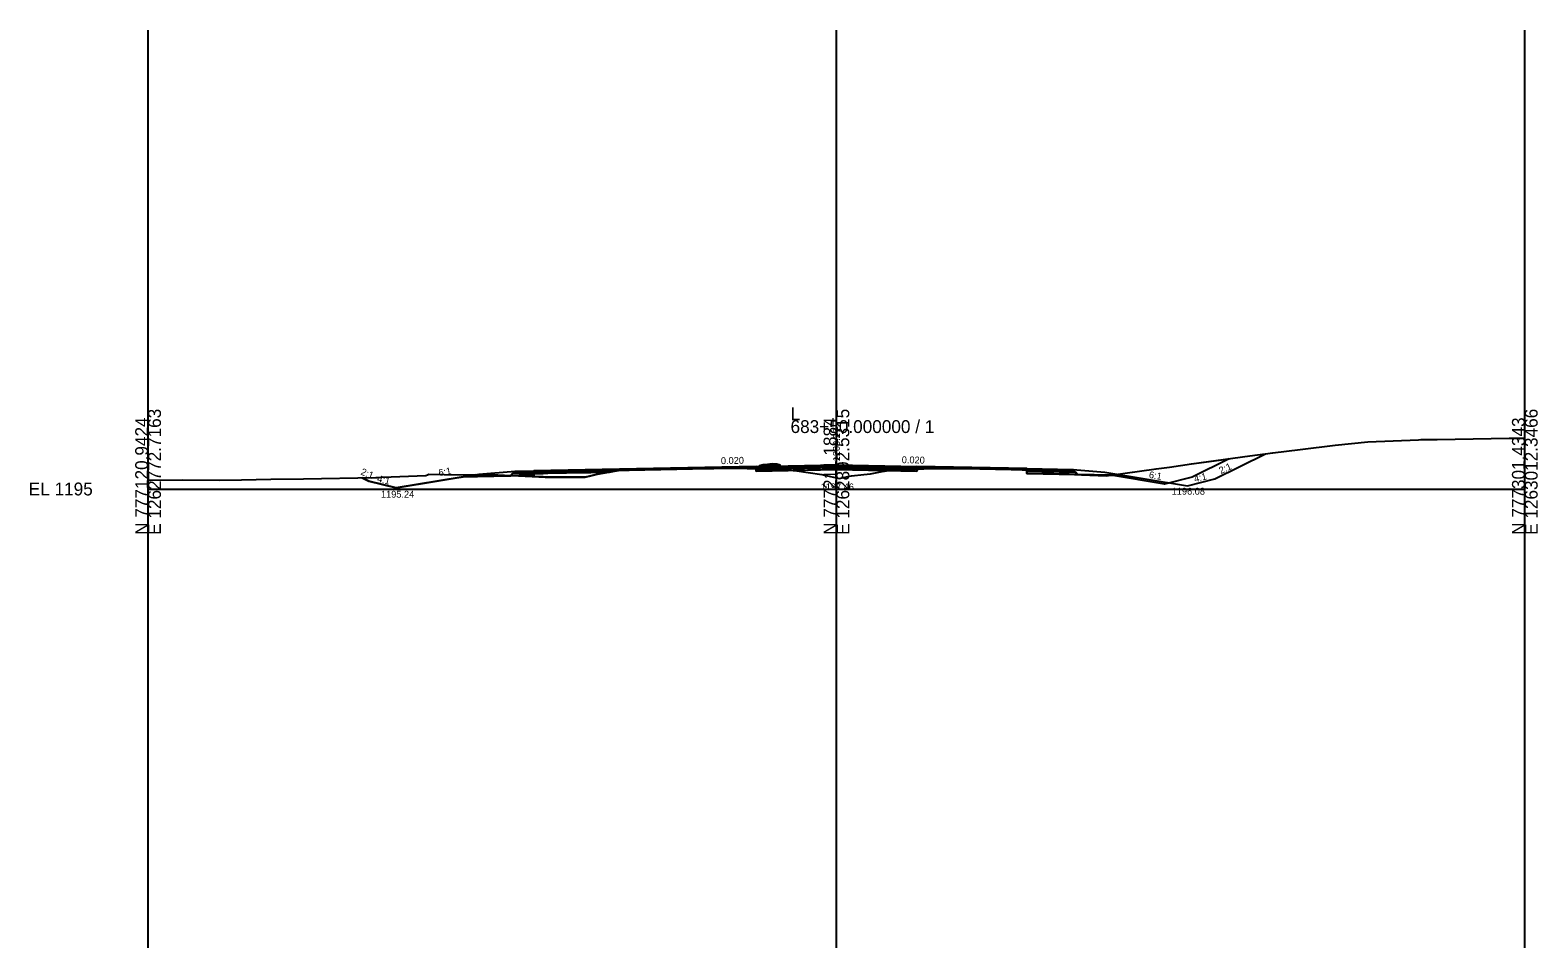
# Model space of a CAD drawing. Extents: x -41 to 1262860, y -100 to 777489.
# Drawn here: x 974.3 to 1302.8, y 330 to 530 of the extents above; entities that cross this region are included whole.
import ezdxf

# ---------------------------------------------------------------- set-up
doc = ezdxf.new("R2010")
doc.units = 0
for name, color, linetype in [('Exist Cross Section Cell', 7, 'Continuous'), ('Exist XS Center Line Elevation Label', 7, 'Continuous'), ('Exist XS Ground Line', 7, 'Continuous'), ('Prop CMT Pvmt Course 1', 7, 'Continuous'), ('Prop CMT Pvmt Surface', 7, 'Continuous'), ('Prop CMT Shld Paved Course 1', 7, 'Continuous'), ('Prop CMT Shld Paved Course 2', 7, 'Continuous'), ('Prop CMT Shld Paved Course 4', 7, 'Continuous'), ('Prop CMT Subgrade Earthwork', 7, 'Continuous'), ('Prop Conc Curb and Gutter', 7, 'Continuous'), ('Prop Conc Island Cover', 7, 'Continuous'), ('Prop XS Ditch Standard Text', 7, 'Continuous'), ('Prop XS Earthwork Shape', 7, 'Continuous'), ('Prop XS Exc Vertical Line 1', 7, 'Continuous'), ('Prop XS Exc Vertical Line 2', 7, 'Continuous'), ('Prop XS Exc Vertical Line 3', 7, 'Continuous'), ('Prop XS Finish Grade', 7, 'Continuous'), ('Prop XS Hydro Elevations', 7, 'Continuous'), ('Prop XS SE Text', 7, 'Continuous'), ('Prop XS Side Slope Text', 7, 'Continuous'), ('Scratch_Level_4', 7, 'Continuous'), ('Scratch_Level_6', 7, 'Continuous')]:
    doc.layers.add(name, color=color, linetype=linetype)

msp = doc.modelspace()

# ---------------------------------------------------------------- linework, layer by layer
at = {"layer": 'Exist Cross Section Cell'}
for p, q in [((1150, 430), (1150, 445)), ((1000, 430), (1150, 430)), ((1150, 430), (1300, 430))]:
    msp.add_line(p, q, dxfattribs=at)
at = {"layer": 'Exist XS Ground Line'}
msp.add_lwpolyline([(1000, 431.95), (1000.61, 431.96), (1007.45, 432), (1015.59, 431.96), (1020.38, 432.01), (1026.75, 432.13), (1033.88, 432.24), (1049.62, 432.51), (1050.17, 432.53), (1050.92, 432.55), (1052.97, 432.63), (1060.5, 432.91), (1060.92, 433.12), (1061.15, 433.23), (1064.52, 433.18), (1069.32, 433.12), (1072.47, 433.1), (1076.21, 433.08), (1085.13, 432.67), (1086.12, 432.63), (1086.5, 432.61), (1087.11, 432.59), (1095.24, 432.58), (1096.5, 432.88), (1097.97, 433.26), (1100.43, 433.68), (1102.95, 434.14), (1106.38, 434.2), (1107.34, 434.23), (1107.61, 434.25), (1110.51, 434.43), (1122.21, 434.57), (1123.26, 434.58), (1134.15, 434.42), (1135.14, 434.4), (1139.22, 434.2), (1139.55, 434.18), (1140.88, 434), (1146.81, 433.16), (1148.74, 432.75), (1150.67, 432.31), (1152.48, 432.7), (1153.28, 432.88), (1156, 433.16), (1157.43, 433.33), (1159.95, 433.8), (1161.39, 434.02), (1164.17, 434.19), (1165.36, 434.27), (1169.02, 434.36), (1177.5, 434.54), (1186.41, 434.33), (1189.64, 434.26), (1192.3, 434.1), (1193.19, 434.05), (1194.78, 433.81), (1197.3, 433.35), (1203.43, 433.11), (1203.46, 433.11), (1208.81, 432.9), (1219.67, 434.38), (1222.6, 434.76), (1227.34, 435.5), (1240.06, 437.22), (1245.06, 437.9), (1251.03, 438.62), (1258.65, 439.53), (1265.79, 440.28), (1276.86, 440.74), (1277.37, 440.76), (1277.76, 440.76), (1280.93, 440.82), (1296.61, 441.05), (1300, 441.1)], dxfattribs=at)
at = {"layer": 'Prop CMT Pvmt Course 1'}
for p, q in [((1132.5, 434.67), (1150, 435.02)), ((1150, 435.02), (1167.5, 434.67))]:
    msp.add_line(p, q, dxfattribs=at)
for points in [[(1084.08, 433.95), (1084.08, 433.7), (1084.08, 433.7), (1132.5, 434.67), (1132.5, 434.92), (1132.5, 434.92), (1084.08, 433.95), (1084.08, 433.95), (1084.08, 433.95)], [(1191.5, 434.44), (1191.5, 434.44), (1167.5, 434.92), (1167.5, 434.92), (1167.5, 434.92), (1167.5, 434.67), (1167.5, 434.67), (1191.5, 434.19), (1191.5, 434.44)]]:
    msp.add_lwpolyline(points, dxfattribs=at)
at = {"layer": 'Prop CMT Pvmt Surface'}
for p, q in [((1079.96, 433.87), (1084.08, 433.95)), ((1084.08, 433.95), (1132.5, 434.92)), ((1132.5, 434.92), (1150, 435.27)), ((1150, 435.27), (1167.5, 434.92)), ((1167.5, 434.92), (1191.5, 434.44)), ((1191.5, 434.44), (1201.5, 434.24))]:
    msp.add_line(p, q, dxfattribs=at)
at = {"layer": 'Prop CMT Shld Paved Course 1'}
for p, q in [((1191.5, 434.44), (1191.5, 434.44)), ((1191.5, 434.44), (1191.5, 434.44)), ((1191.5, 434.44), (1191.5, 434.19)), ((1191.5, 434.19), (1191.5, 434.19)), ((1191.5, 434.19), (1201.76, 433.99)), ((1195.5, 434.36), (1195.5, 434.36)), ((1201.76, 433.99), (1201.5, 434.24))]:
    msp.add_line(p, q, dxfattribs=at)
msp.add_lwpolyline([(1079.96, 433.87), (1084.08, 433.95), (1084.08, 433.95), (1084.08, 433.7), (1079.71, 433.62), (1079.71, 433.62), (1079.71, 433.62), (1079.96, 433.87), (1080.08, 433.87)], dxfattribs=at)
at = {"layer": 'Prop CMT Shld Paved Course 2'}
for p, q in [((1085.13, 433.72), (1084.08, 433.7)), ((1084.08, 433.7), (1084.08, 433.7)), ((1084.08, 433.7), (1084.08, 433.7)), ((1084.08, 433.7), (1084.08, 433.37)), ((1086.12, 433.74), (1085.13, 433.72)), ((1086.5, 433.75), (1086.12, 433.74)), ((1087.11, 433.76), (1086.5, 433.75)), ((1095.24, 433.93), (1087.11, 433.76)), ((1087.11, 433.76), (1087.11, 433.76)), ((1087.11, 433.76), (1087.11, 433.76)), ((1087.11, 433.76), (1087.11, 433.76)), ((1096.5, 433.95), (1095.24, 433.93)), ((1095.24, 433.93), (1095.24, 433.93)), ((1097.97, 433.98), (1096.5, 433.95)), ((1096.5, 433.95), (1096.5, 433.95)), ((1100.43, 434.03), (1097.97, 433.98)), ((1097.97, 433.98), (1097.97, 433.98)), ((1097.97, 433.98), (1097.97, 433.98)), ((1097.97, 433.65), (1100.43, 433.7)), ((1102.95, 434.08), (1100.43, 434.03)), ((1100.43, 434.03), (1100.43, 434.03)), ((1100.43, 433.7), (1100.43, 433.7)), ((1100.43, 433.7), (1100.56, 433.7)), ((1100.56, 433.7), (1102.6, 434.07)), ((1100.56, 433.7), (1100.56, 433.7)), ((1102.6, 434.07), (1102.95, 434.08)), ((1102.6, 434.07), (1102.6, 434.07)), ((1106.38, 434.15), (1102.95, 434.08)), ((1102.95, 434.08), (1106.38, 434.15)), ((1102.95, 434.08), (1102.95, 434.08)), ((1102.95, 434.08), (1102.95, 434.08)), ((1107.34, 434.17), (1106.38, 434.15)), ((1106.38, 434.15), (1107.34, 434.17)), ((1106.38, 434.15), (1106.38, 434.15)), ((1106.38, 434.15), (1106.38, 434.15)), ((1107.61, 434.17), (1107.34, 434.17)), ((1107.34, 434.17), (1107.61, 434.17)), ((1110.51, 434.23), (1107.61, 434.17)), ((1107.61, 434.17), (1110.51, 434.23)), ((1107.61, 434.17), (1107.61, 434.17)), ((1107.61, 434.17), (1107.61, 434.17)), ((1122.21, 434.47), (1110.51, 434.23)), ((1110.51, 434.23), (1122.21, 434.47)), ((1110.51, 434.23), (1110.51, 434.23)), ((1110.51, 434.23), (1110.51, 434.23)), ((1110.51, 434.23), (1110.51, 434.23)), ((1110.51, 434.23), (1110.51, 434.23)), ((1123.26, 434.49), (1122.21, 434.47)), ((1122.21, 434.47), (1123.26, 434.49)), ((1122.21, 434.47), (1122.21, 434.47)), ((1122.21, 434.47), (1122.21, 434.47)), ((1132.5, 434.67), (1123.26, 434.49)), ((1123.26, 434.49), (1125.9, 434.54)), ((1123.26, 434.49), (1123.26, 434.49)), ((1125.9, 434.54), (1125.9, 434.54)), ((1125.9, 434.54), (1125.9, 434.54)), ((1125.9, 434.54), (1132.5, 434.44)), ((1132.5, 434.34), (1150, 434.69)), ((1132.5, 434.44), (1132.5, 434.67)), ((1132.5, 434.67), (1132.5, 434.67)), ((1132.5, 434.67), (1132.5, 434.67)), ((1132.5, 434.44), (1132.5, 434.34)), ((1132.5, 434.44), (1132.5, 434.44)), ((1150, 434.69), (1167.5, 434.34)), ((1169.02, 434.64), (1167.5, 434.67)), ((1167.5, 434.67), (1167.5, 434.67)), ((1167.5, 434.67), (1167.5, 434.34)), ((1167.5, 434.34), (1167.9, 434.33)), ((1167.9, 434.33), (1169.02, 434.36)), ((1167.9, 434.33), (1167.9, 434.33)), ((1177.5, 434.47), (1169.02, 434.64)), ((1169.02, 434.64), (1169.02, 434.64)), ((1169.02, 434.36), (1175.93, 434.5)), ((1169.02, 434.36), (1169.02, 434.36)), ((1175.93, 434.5), (1175.93, 434.5)), ((1175.93, 434.5), (1177.5, 434.47)), ((1186.41, 434.29), (1177.5, 434.47)), ((1177.5, 434.47), (1177.5, 434.47)), ((1177.5, 434.47), (1177.5, 434.47)), ((1177.5, 434.47), (1177.5, 434.47)), ((1177.5, 434.47), (1177.5, 434.47)), ((1177.5, 434.47), (1186.41, 434.29)), ((1189.64, 434.23), (1186.41, 434.29)), ((1186.41, 434.29), (1186.41, 434.29)), ((1186.41, 434.29), (1186.41, 434.29)), ((1186.41, 434.29), (1189.64, 434.23)), ((1191.5, 434.19), (1189.64, 434.23)), ((1189.64, 434.23), (1189.64, 434.23)), ((1189.64, 434.23), (1189.64, 434.23)), ((1189.64, 434.23), (1190.44, 434.21)), ((1190.44, 434.21), (1190.44, 434.21)), ((1190.44, 434.21), (1191.5, 434.15)), ((1191.5, 434.19), (1191.5, 434.19)), ((1191.5, 434.19), (1191.5, 434.19)), ((1191.5, 434.19), (1191.5, 433.86)), ((1191.5, 434.15), (1191.5, 434.19)), ((1191.5, 434.19), (1191.5, 434.19)), ((1191.5, 434.19), (1191.5, 434.19)), ((1191.5, 434.15), (1191.5, 434.15)), ((1191.5, 433.86), (1191.5, 433.86)), ((1191.5, 433.86), (1202.1, 433.65)), ((1202.1, 433.65), (1201.76, 433.99)), ((1084.08, 433.37), (1085.13, 433.39)), ((1084.08, 433.37), (1084.08, 433.37)), ((1085.13, 433.39), (1086.12, 433.41)), ((1086.12, 433.41), (1086.5, 433.42)), ((1086.5, 433.42), (1087.11, 433.43)), ((1087.11, 433.43), (1095.24, 433.59)), ((1087.11, 433.43), (1087.11, 433.43)), ((1087.11, 433.43), (1087.11, 433.43)), ((1087.11, 433.43), (1087.11, 433.43)), ((1095.24, 433.59), (1096.5, 433.62)), ((1095.24, 433.59), (1095.24, 433.59)), ((1096.5, 433.62), (1097.97, 433.65)), ((1096.5, 433.62), (1096.5, 433.62)), ((1097.97, 433.65), (1097.97, 433.65)), ((1097.97, 433.65), (1097.97, 433.65))]:
    msp.add_line(p, q, dxfattribs=at)
msp.add_lwpolyline([(1079.71, 433.62), (1084.08, 433.7), (1084.08, 433.7), (1084.08, 433.37), (1079.37, 433.28), (1079.37, 433.28), (1079.37, 433.28), (1079.71, 433.62), (1079.83, 433.62)], dxfattribs=at)
at = {"layer": 'Prop CMT Shld Paved Course 4'}
for p, q in [((1100.43, 433.68), (1097.97, 433.26)), ((1100.56, 433.7), (1100.43, 433.68)), ((1132.5, 434.34), (1132.5, 433.88)), ((1132.5, 433.88), (1150, 434.23)), ((1150, 434.23), (1167.5, 433.88)), ((1167.5, 434.34), (1167.5, 433.88)), ((1167.9, 434.33), (1167.5, 434.32)), ((1191.5, 433.86), (1191.5, 433.86)), ((1191.5, 433.86), (1191.5, 433.86)), ((1191.5, 433.86), (1191.5, 433.4)), ((1085.13, 432.67), (1084.08, 432.72)), ((1086.12, 432.63), (1085.13, 432.67)), ((1086.5, 432.61), (1086.12, 432.63)), ((1087.11, 432.59), (1086.5, 432.61)), ((1095.24, 432.58), (1087.11, 432.59)), ((1096.5, 432.88), (1095.24, 432.58)), ((1097.97, 433.26), (1096.5, 432.88)), ((1191.5, 433.4), (1204.56, 433.14)), ((1202.56, 433.18), (1202.1, 433.65))]:
    msp.add_line(p, q, dxfattribs=at)
msp.add_lwpolyline([(1079.37, 433.28), (1084.08, 433.37), (1084.08, 433.37), (1084.08, 432.91), (1078.9, 432.81), (1078.9, 432.81), (1078.9, 432.81), (1079.37, 433.28), (1079.37, 433.28), (1079.37, 433.28), (1079.49, 433.28)], dxfattribs=at)
at = {"layer": 'Prop CMT Subgrade Earthwork'}
for p, q in [((1132.5, 434.44), (1132.5, 433.88)), ((1132.5, 433.88), (1150, 434.23)), ((1150, 434.23), (1167.5, 433.88)), ((1167.5, 433.88), (1167.5, 434.32)), ((1191.5, 434.15), (1191.5, 433.4)), ((1084.08, 432.91), (1068.2, 432.59)), ((1084.08, 432.91), (1084.08, 432.72)), ((1191.5, 433.4), (1212.73, 432.97))]:
    msp.add_line(p, q, dxfattribs=at)
at = {"layer": 'Prop Conc Curb and Gutter'}
for p, q in [((1133.25, 434.94), (1133.26, 435.1)), ((1133.25, 434.94), (1133.25, 434.94)), ((1133.25, 434.94), (1133.25, 434.81)), ((1135.01, 434.94), (1133.25, 434.94)), ((1133.25, 434.94), (1133.25, 434.94)), ((1133.25, 434.81), (1133.25, 434.81)), ((1133.25, 434.81), (1135.01, 434.81)), ((1133.26, 435.1), (1134.01, 435.35)), ((1133.26, 435.1), (1133.26, 435.1)), ((1134.01, 435.35), (1135.01, 435.37)), ((1134.01, 435.35), (1134.01, 435.35)), ((1135.01, 435.37), (1135.01, 434.94)), ((1135.01, 434.81), (1135.01, 434.94)), ((1135.01, 434.94), (1135.01, 434.94)), ((1135.01, 434.81), (1135.01, 434.81)), ((1135.01, 434.81), (1135.01, 434.81)), ((1137.02, 435.44), (1136.02, 435.46)), ((1136.02, 435.46), (1136.02, 435.03)), ((1137.78, 435.03), (1136.02, 435.03)), ((1136.02, 435.03), (1136.02, 434.9)), ((1136.02, 435.03), (1136.02, 435.03)), ((1136.02, 434.9), (1136.02, 434.9)), ((1136.02, 434.9), (1137.78, 434.9)), ((1137.77, 435.19), (1137.02, 435.44)), ((1137.02, 435.44), (1137.02, 435.44)), ((1137.78, 435.03), (1137.77, 435.19)), ((1137.77, 435.19), (1137.77, 435.19)), ((1137.78, 434.9), (1137.78, 435.03)), ((1137.78, 435.03), (1137.78, 435.03)), ((1137.78, 435.03), (1137.78, 435.03)), ((1137.78, 434.9), (1137.78, 434.9)), ((1137.78, 434.9), (1137.78, 434.9))]:
    msp.add_line(p, q, dxfattribs=at)
at = {"layer": 'Prop Conc Island Cover'}
for p, q in [((1136.02, 435.46), (1135.01, 435.37)), ((1135.01, 435.37), (1135.01, 435.12)), ((1136.02, 435.21), (1135.01, 435.12)), ((1136.02, 435.21), (1136.02, 435.46)), ((1136.02, 435.46), (1136.02, 435.46)), ((1136.02, 435.21), (1136.02, 435.21))]:
    msp.add_line(p, q, dxfattribs=at)
at = {"layer": 'Prop XS Earthwork Shape'}
for points in [[(1132.5, 434.44), (1134.15, 434.42), (1135.14, 434.4), (1139.22, 434.2), (1139.55, 434.18), (1140.57, 434.04), (1132.5, 433.88)], [(1140.57, 434.04), (1140.88, 434), (1146.81, 433.16), (1148.74, 432.75), (1150.67, 432.31), (1152.48, 432.7), (1153.28, 432.88), (1156, 433.16), (1157.43, 433.33), (1159.95, 433.8), (1161.26, 434), (1150, 434.23)], [(1161.26, 434), (1167.5, 433.88), (1167.5, 434.32), (1165.36, 434.27), (1164.17, 434.19), (1161.39, 434.02)], [(1197.3, 433.35), (1200.72, 433.21), (1191.5, 433.4), (1191.5, 434.15), (1192.3, 434.1), (1193.19, 434.05), (1194.78, 433.81)], [(1227.34, 435.5), (1235.56, 436.61), (1227.5, 432.58), (1221.5, 431.08), (1209.8, 433.03), (1219.67, 434.38), (1222.6, 434.76)], [(1069.32, 433.12), (1071.28, 433.11), (1068.2, 432.59), (1054.08, 430.24), (1048.08, 431.74), (1046.64, 432.46), (1049.62, 432.51), (1050.17, 432.53), (1050.92, 432.55), (1052.97, 432.63), (1060.5, 432.91), (1060.92, 433.12), (1061.15, 433.23), (1064.52, 433.18)], [(1071.28, 433.11), (1072.47, 433.1), (1076.21, 433.08), (1079.04, 432.95), (1078.9, 432.81), (1068.2, 432.59)], [(1078.9, 432.81), (1079.04, 432.95), (1081.17, 432.85)], [(1081.17, 432.85), (1084.08, 432.72), (1084.08, 432.91)], [(1203.46, 433.11), (1208.81, 432.9), (1209.8, 433.03), (1209.78, 433.03), (1202.56, 433.18), (1200.72, 433.21), (1203.43, 433.11)]]:
    msp.add_lwpolyline(points, close=True, dxfattribs=at)
at = {"layer": 'Prop XS Exc Vertical Line 1'}
msp.add_line((1000, 330), (1000, 530), dxfattribs=at)
at = {"layer": 'Prop XS Exc Vertical Line 2'}
msp.add_line((1150, 330), (1150, 530), dxfattribs=at)
at = {"layer": 'Prop XS Exc Vertical Line 3'}
msp.add_line((1300, 330), (1300, 530), dxfattribs=at)
at = {"layer": 'Prop XS Finish Grade'}
for p, q in [((1232.48, 432.18), (1243.49, 437.69)), ((1072.08, 433.24), (1079.96, 433.87)), ((1078.9, 432.81), (1079.96, 433.87)), ((1201.5, 434.24), (1208.48, 433.68)), ((1202.56, 433.18), (1201.5, 434.24)), ((1208.48, 433.68), (1226.48, 430.68)), ((1046.64, 432.46), (1048.08, 431.74)), ((1048.08, 431.74), (1054.08, 430.24)), ((1054.08, 430.24), (1072.08, 433.24)), ((1226.48, 430.68), (1232.48, 432.18))]:
    msp.add_line(p, q, dxfattribs=at)
at = {"layer": 'Scratch_Level_4'}
msp.add_line((1300, 330), (1300, 530), dxfattribs=at)
at = {"layer": 'Scratch_Level_6'}
msp.add_line((1000, 330), (1000, 530), dxfattribs=at)

# ---------------------------------------------------------------- texts
at = {"layer": 'Exist Cross Section Cell'}
for s, p in [('E 1262772.7163', (1002.8, 420)), ('E 1262892.5315', (1152.8, 420)), ('E 1263012.3466', (1302.8, 420)), ('N 777120.9424', (1000, 420)), ('N 777211.1884', (1150, 420)), ('N 777301.4343', (1300, 420))]:
    msp.add_text(s, height=2.8, rotation=90, dxfattribs=at).set_placement(p)
for s, p in [('L', (1140, 445)), ('683+50.000000 / 1', (1140, 442.2)), ('EL 1195', (974, 428.6))]:
    msp.add_text(s, height=2.8, dxfattribs=at).set_placement(p)
at = {"layer": 'Exist XS Center Line Elevation Label'}
msp.add_text('1197.46', height=1.5, dxfattribs=at).set_placement((1146.56, 429.71))
at = {"layer": 'Prop XS Ditch Standard Text'}
for s, p in [('1195.24', (1050.75, 428.11)), ('1196.08', (1223.05, 428.76))]:
    msp.add_text(s, height=1.5, dxfattribs=at).set_placement(p)
at = {"layer": 'Prop XS Hydro Elevations'}
msp.add_text('1200.27', height=1.5, rotation=90, dxfattribs=at).set_placement((1150.75, 436.03))
at = {"layer": 'Prop XS SE Text'}
for rotation, p in [(1.1458, (1124.84, 435.41)), (358.8542, (1164.22, 435.63))]:
    msp.add_text('0.020', height=1.5, rotation=rotation, dxfattribs=at).set_placement(p)
at = {"layer": 'Prop XS Side Slope Text'}
for s, rotation, p in [('2:1', 338.2726, (1046.21, 433.19)), ('6:1', 9.4623, (1063.41, 432.8)), ('6:1', 350.5377, (1218.01, 432.42)), ('2:1', 24.7387, (1233.76, 433.24)), ('4:1', 345.9638, (1049.83, 431.61)), ('4:1', 14.0362, (1228.11, 431.44))]:
    msp.add_text(s, height=1.5, rotation=rotation, dxfattribs=at).set_placement(p)

doc.saveas('drawing.dxf')
